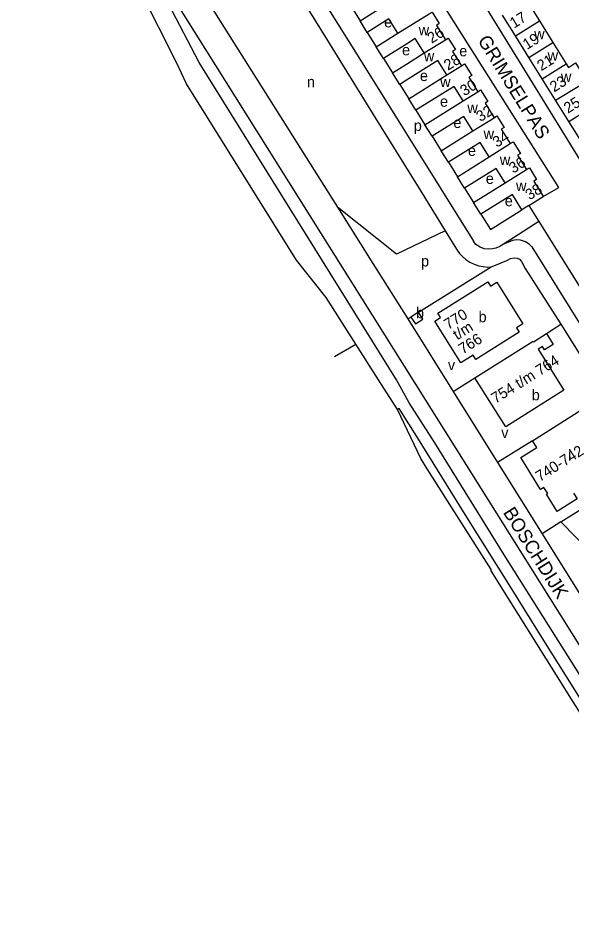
# Model space of a CAD drawing. Extents: x 158848 to 160613, y 385889 to 387762.
# Drawn here: x 158856.4 to 159061.2, y 386783.5 to 387116.4 of the extents above; entities that cross this region are included whole.
import ezdxf

# ---------------------------------------------------------------- set-up
doc = ezdxf.new("R2010")
doc.units = 0
for name, color, linetype in [('BLT_Basislijn', 7, 'Continuous'), ('BLT_Bebouwing', 7, 'Continuous'), ('BLT_Centroide', 7, 'Continuous'), ('BLT_Huisnummer', 7, 'Continuous'), ('BLT_Huisnummer_ tussenligend', 7, 'Continuous'), ('BLT_Huisnummer_reeks', 7, 'Continuous'), ('BLT_Onderverdeling_panden', 7, 'Continuous'), ('BLT_Straatnaam', 7, 'Continuous'), ('BLT_Vlakafsluiter', 7, 'Continuous')]:
    doc.layers.add(name, color=color, linetype=linetype)

msp = doc.modelspace()

# ---------------------------------------------------------------- linework, layer by layer
at = {"layer": 'BLT_Basislijn'}
for p, q in [((158904.33, 387138.99), (159120.99, 386793.5)), ((158961.09, 387135.91), (158980.54, 387104.75)), ((158979.52, 387120.71), (158982.85, 387115.38)), ((158985.52, 387111.11), (158988.85, 387105.79)), ((158980.54, 387104.75), (159000, 387073.6)), ((158991.52, 387101.51), (158994.84, 387096.2)), ((158997.51, 387091.92), (159000.84, 387086.59)), ((159003.51, 387082.32), (159006.83, 387076.99)), ((159000, 387073.6), (159024.74, 387033.99)), ((159009.51, 387072.71), (159012.83, 387067.4)), ((159015.5, 387063.12), (159018.83, 387057.8)), ((159021.49, 387053.54), (159024.82, 387048.2)), ((159045.19, 387047.19), (159048.9, 387041.26)), ((158996.37, 387029.14), (158974.53, 387046.48)), ((159048.9, 387041.26), (159085.5, 386982.75)), ((159014.34, 387037.74), (158996.37, 387029.14)), ((159035.85, 387032.84), (159034.68, 387032.12)), ((159004.47, 387007.7), (159031.36, 387024.52)), ((159000.54, 387005.27), (159001.68, 387005.94)), ((159000.54, 387005.27), (159017.27, 386978.47)), ((159051.79, 386999.81), (159057.02, 387003.3)), ((159017.27, 386978.47), (159025.34, 386983.5)), ((159046.56, 386960.21), (159033.69, 386952.18)), ((159057.03, 386930.2), (159050.12, 386925.88))]:
    msp.add_line(p, q, dxfattribs=at)
for points in [[(158981.27, 386995.93), (158970.33, 387013.12), (158959.33, 387027), (158918.71, 387092.14), (158915.02, 387100), (158901.75, 387126.26), (158867.81, 387181.73), (158857.76, 387197.35), (158856.39, 387201.34), (158856.42, 387203.96), (158857.49, 387207.05), (158861.21, 387210.57)], [(159050.58, 387050.53), (159056.34, 387053.79), (158996.99, 387147.73)], [(159045.59, 387144.62), (159023.02, 387130.63), (159066.15, 387060.6), (159091.98, 387076.44)], [(158996.31, 386982.75), (158923.31, 387100), (158910.6, 387124.57), (158904.33, 387138.99)], [(158953.1, 387136.81), (158970.77, 387108.07), (158987.74, 387080.74), (159004.66, 387053.41), (159014.34, 387037.74)], [(158927.58, 387120.88), (158974.53, 387046.48)], [(158974.53, 387046.48), (158987.62, 387025.73)], [(159027.5, 387043.92), (159031.1, 387038.34), (159042.64, 387045.6)], [(159048.9, 387041.26), (159039.64, 387035.18), (159035.85, 387032.84)], [(159014.34, 387037.74), (159018.5, 387031), (159019.6, 387029.45), (159020.71, 387028.29), (159021.98, 387027.18), (159023.49, 387026.2), (159025, 387025.44), (159026.8, 387024.8), (159028.31, 387024.57), (159029.99, 387024.4), (159031.36, 387024.52)], [(159034.68, 387032.12), (159034.51, 387032.02), (159032.99, 387031.39), (159031.81, 387031.12), (159030.42, 387030.98), (159028.76, 387031.19), (159027.24, 387031.74), (159025.71, 387032.71), (159024.74, 387033.99)], [(159046.34, 387031.9), (159045.4, 387032.88), (159044.06, 387033.75), (159042.2, 387034.39), (159040.75, 387034.5), (159039.24, 387034.27), (159037.5, 387033.52), (159035.85, 387032.84)], [(159046.34, 387031.9), (159087.93, 386965.22), (159109.13, 386930.56)], [(159031.36, 387024.52), (159032.96, 387025.09), (159037.08, 387026.84), (159038.49, 387027.59), (159039.82, 387027.82), (159040.93, 387027.65), (159041.74, 387027.3), (159042.49, 387026.49), (159043.95, 387023.87)], [(158987.62, 387025.73), (159000.54, 387005.27)], [(159043.95, 387023.87), (159057.02, 387003.3)], [(159057.02, 387003.3), (159066.55, 386988.18), (159073.27, 386976.95)], [(158996.64, 386971.75), (158989.64, 386982.75), (158981.27, 386995.93)], [(159087.51, 386836.33), (159070.34, 386863.72), (159036.18, 386918.09), (159010.5, 386959.48), (159001.01, 386974.19), (158996.31, 386982.75)], [(159017.27, 386978.47), (159033.69, 386952.18)], [(159118.96, 386784.97), (159105.25, 386806.83), (159102.49, 386810.72), (159099.1, 386814.04), (159093.62, 386819.34), (159087.91, 386827.34), (159070.38, 386855.24), (159050.78, 386886.4), (159039.05, 386905.23), (159021.73, 386932.99), (159004.41, 386960.75), (158997.31, 386972.17), (158996.64, 386971.75)], [(159116.48, 386783.5), (159108.47, 386793.51), (159099.44, 386805.03), (159095.71, 386810.66), (159061.69, 386863.68), (159031.37, 386912.11), (159031.31, 386912.59), (159007.61, 386949.8), (159005.38, 386953.68), (158996.64, 386971.75)], [(159033.69, 386952.18), (159050.12, 386925.88)], [(159050.12, 386925.88), (159066.54, 386899.59)]]:
    msp.add_lwpolyline(points, dxfattribs=at)
at = {"layer": 'BLT_Bebouwing'}
for p, q in [((158982.85, 387115.38), (158990.91, 387120.42)), ((159044.35, 387123.05), (159049.14, 387115.38)), ((159040.27, 387109.85), (159035.48, 387117.51)), ((158985.52, 387111.11), (158982.85, 387115.38)), ((159049.14, 387115.38), (159054.17, 387107.32)), ((158988.85, 387105.79), (158996.85, 387110.79)), ((159045.31, 387101.79), (159040.27, 387109.85)), ((159054.17, 387107.32), (159059.09, 387099.46)), ((158991.52, 387101.51), (158988.85, 387105.79)), ((159000, 387106.81), (158991.52, 387101.51)), ((159000, 387099.42), (159006.55, 387103.51)), ((159050.22, 387093.92), (159045.31, 387101.79)), ((158994.84, 387096.2), (159000, 387099.42)), ((158997.51, 387091.92), (158994.84, 387096.2)), ((159000.84, 387086.59), (159014.99, 387095.43)), ((159055.13, 387086.06), (159050.22, 387093.92)), ((159000, 387093.48), (158997.51, 387091.92)), ((159003.51, 387082.32), (159000.84, 387086.59)), ((159006.83, 387076.99), (159020.98, 387085.83)), ((159060.04, 387078.2), (159055.13, 387086.06)), ((159009.51, 387072.71), (159006.83, 387076.99)), ((159065.05, 387070.21), (159060.04, 387078.2)), ((159012.83, 387067.4), (159024.55, 387074.72)), ((159015.5, 387063.12), (159012.83, 387067.4)), ((159018.83, 387057.8), (159030.54, 387065.12)), ((159021.49, 387053.54), (159018.83, 387057.8)), ((159024.82, 387048.2), (159036.54, 387055.52)), ((159045.19, 387047.19), (159050.58, 387050.53)), ((159027.5, 387043.92), (159024.82, 387048.2)), ((159045.19, 387047.19), (159042.64, 387045.6)), ((159004.47, 387007.7), (159001.68, 387005.94))]:
    msp.add_line(p, q, dxfattribs=at)
for points in [[(159008.41, 387117.97), (159009.46, 387118.62), (159012.14, 387114.36), (159011.09, 387113.7), (159014.41, 387108.38)], [(158996.85, 387110.79), (158993.52, 387116.11), (158985.52, 387111.11)], [(159006.55, 387103.51), (159003.23, 387108.83), (159000, 387106.81)], [(159014.41, 387108.38), (159015.46, 387109.03), (159018.13, 387104.76), (159017.08, 387104.11), (159020.4, 387098.79)], [(159014.99, 387095.43), (159011.66, 387100.76), (159000, 387093.48)], [(159020.4, 387098.79), (159021.45, 387099.45), (159024.12, 387095.17), (159023.07, 387094.51), (159026.39, 387089.2)], [(159059.09, 387099.46), (159059.89, 387098.18), (159062.53, 387099.82), (159066.74, 387093.06), (159064.1, 387091.43)], [(159020.98, 387085.83), (159017.65, 387091.15), (159003.51, 387082.32)], [(159026.39, 387089.2), (159027.44, 387089.85), (159030.12, 387085.57), (159029.07, 387084.91), (159032.39, 387079.59)], [(159024.55, 387074.72), (159021.23, 387080.03), (159009.51, 387072.71)], [(159032.39, 387079.59), (159033.44, 387080.25), (159036.12, 387075.97), (159035.06, 387075.31), (159038.38, 387070)], [(159030.54, 387065.12), (159027.22, 387070.44), (159015.5, 387063.12)], [(159038.38, 387070), (159039.43, 387070.65), (159042.11, 387066.37), (159041.06, 387065.71), (159044.39, 387060.39)], [(159036.54, 387055.52), (159033.21, 387060.85), (159021.49, 387053.54)], [(159044.39, 387060.39), (159045.44, 387061.05), (159048.11, 387056.78), (159047.07, 387056.12), (159050.58, 387050.53)], [(159042.64, 387045.6), (159039.16, 387051.19), (159027.5, 387043.92)], [(159012.59, 387005.77), (159011.56, 387007.42), (159030.05, 387018.97), (159031.07, 387017.34), (159033.36, 387018.78)], [(159033.36, 387018.78), (159042.97, 387003.41), (159040.69, 387001.97), (159041.72, 387000.32), (159025.67, 386990.25), (159024.62, 386991.9)], [(159001.68, 387005.94), (159003.3, 387003.39), (159006.09, 387005.15), (159004.47, 387007.7)], [(159024.62, 386991.9), (159020.09, 386989.07), (159010.48, 387004.43), (159012.59, 387005.77)], [(159051.79, 386999.81), (159054.28, 386995.84), (159051.07, 386993.82), (159050.27, 386995.09), (159048.65, 386994.07), (159058.21, 386978.86), (159036.7, 386965.37), (159025.34, 386983.5)], [(159046.82, 386996.98), (159046.95, 386996.77), (159051.79, 386999.81)], [(159025.34, 386983.5), (159046.82, 386996.98)], [(159046.56, 386960.21), (159064.89, 386971.73)], [(159061.8, 386940.82), (159063.11, 386938.73), (159055.72, 386934.1), (159051.8, 386940.45), (159052.23, 386940.71), (159050.82, 386942.99), (159049.6, 386942.22), (159042.24, 386953.97), (159048.15, 386957.67), (159046.56, 386960.21)], [(159085.73, 386948.14), (159098.9, 386927.04), (159092.29, 386920.79), (159087.65, 386923.14), (159084.24, 386916.4), (159079.6, 386918.78), (159073.85, 386913.11), (159057.03, 386930.2)], [(159057.03, 386930.2), (159081.24, 386945.33)]]:
    msp.add_lwpolyline(points, dxfattribs=at)
at = {"layer": 'BLT_Onderverdeling_panden'}
for p, q in [((158996.85, 387110.79), (159008.41, 387117.97)), ((159040.27, 387109.85), (159049.14, 387115.38)), ((159006.55, 387103.51), (159014.41, 387108.38)), ((159045.31, 387101.79), (159054.17, 387107.32)), ((159014.99, 387095.43), (159020.4, 387098.79)), ((159050.22, 387093.92), (159059.09, 387099.46)), ((159055.13, 387086.06), (159064.1, 387091.43)), ((159020.98, 387085.83), (159026.39, 387089.2)), ((159060.04, 387078.2), (159068.91, 387083.74)), ((159024.55, 387074.72), (159032.39, 387079.59)), ((159030.54, 387065.12), (159038.38, 387070)), ((159036.54, 387055.52), (159044.39, 387060.39))]:
    msp.add_line(p, q, dxfattribs=at)
at = {"layer": 'BLT_Vlakafsluiter'}
msp.add_line((158973.44, 386991.41), (158981.27, 386995.93), dxfattribs=at)

# ---------------------------------------------------------------- texts
at = {"layer": 'BLT_Centroide'}
for s, p in [('e', (158991.76, 387112.96)), ('w', (159004.53, 387110.06)), ('w', (159047.23, 387108.59)), ('e', (158998.37, 387102.64)), ('e', (159019.51, 387102.27)), ('w', (159052.2, 387100.62)), ('w', (159006.45, 387100.47)), ('n', (158963.2, 387090.84)), ('e', (159004.97, 387093.13)), ('w', (159012.46, 387090.88)), ('w', (159057.11, 387092.75)), ('e', (159012.41, 387083.63)), ('w', (159022.52, 387081.28)), ('p', (159002.71, 387074.73)), ('e', (159017.36, 387075.78)), ('w', (159028.52, 387071.69)), ('e', (159022.73, 387065.46)), ('w', (159034.52, 387062.09)), ('e', (159029.34, 387055.13)), ('w', (159040.51, 387052.47)), ('e', (159036.36, 387046.87)), ('p', (159005.4, 387024.62)), ('b', (159003.52, 387005.5)), ('b', (159026.66, 387004.03)), ('v', (159015.33, 386986.3)), ('b', (159046.33, 386975.16)), ('v', (159035.04, 386961.2)), ('i', (159059.73, 386952.91))]:
    msp.add_text(s, height=4, dxfattribs=at).set_placement(p)
at = {"layer": 'BLT_Huisnummer'}
for s, rotation, p in [('26', 32.0119, (159009.31, 387106.89)), ('19', 31.9835, (159044.56, 387104.59)), ('23', 31.9835, (159054.58, 387088.87)), ('30', 32.0119, (159021.42, 387087.44)), ('34', 32.0119, (159033.43, 387068.45)), ('38', 32.0119, (159045.52, 387049))]:
    msp.add_text(s, height=4, rotation=rotation, dxfattribs=at).set_placement(p)
at = {"layer": 'BLT_Huisnummer_ tussenligend'}
for s, rotation, p in [('17', 31.9835, (159039.76, 387112.46)), ('28', 32.0119, (159015.38, 387096.9)), ('21', 31.9835, (159049.83, 387096.7)), ('25', 31.9835, (159059.7, 387081.05)), ('32', 32.0119, (159027.35, 387077.93)), ('36', 32.0119, (159039.47, 387058.86))]:
    msp.add_text(s, height=4, rotation=rotation, dxfattribs=at).set_placement(p)
at = {"layer": 'BLT_Huisnummer_reeks'}
for s, rotation, p in [('770', 31.9847, (159015.43, 387001.13)), ('t/m', 31.9847, (159018.77, 386997.29)), ('766', 31.9847, (159020.84, 386992.07)), ('754 t/m 764', 32.0941, (159032.94, 386973.82)), ('740-742', 32.3598, (159049.32, 386944.94))]:
    msp.add_text(s, height=4, rotation=rotation, dxfattribs=at).set_placement(p)
at = {"layer": 'BLT_Straatnaam'}
for s, rotation, p in [('GRIMSELPAS', 301.7846, (159026.17, 387108.17)), ('BOSCHDIJK', 302.2071, (159035.56, 386933.73))]:
    msp.add_text(s, height=5, rotation=rotation, dxfattribs=at).set_placement(p)

doc.saveas('drawing.dxf')
